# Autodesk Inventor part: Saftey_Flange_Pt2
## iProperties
Shininess: 64.0
Length Units: 11269
Angle Units: 11279
Time Units: 11290
Mass Units: 11283
Length Display Precision: 3
Angle Display Precision: 2
Compacted: True
Part Number: Saftey_Flange_Pt2
Document SubType Name: Modeling
Created: 2004-07
Designer: John Blackburn
Manufacturer: Standard
Standards Organization: Custom
Project: Mucap
Material: Stainless Steel, Austenitic
Description: Mucap, Be Window, Saftey Flange
Density: 0.0
Volumn: 0.0
Area: 0.0
PropertySet Name: Model Information
Control State: 0
Master: False
Checked Out: False
Author: John Blackburn
Title: Mucap, Saftey Flange, DN25KF
Subject: Mucap
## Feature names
1. Revolution1
2. Chamfer2
3. Fillet1
